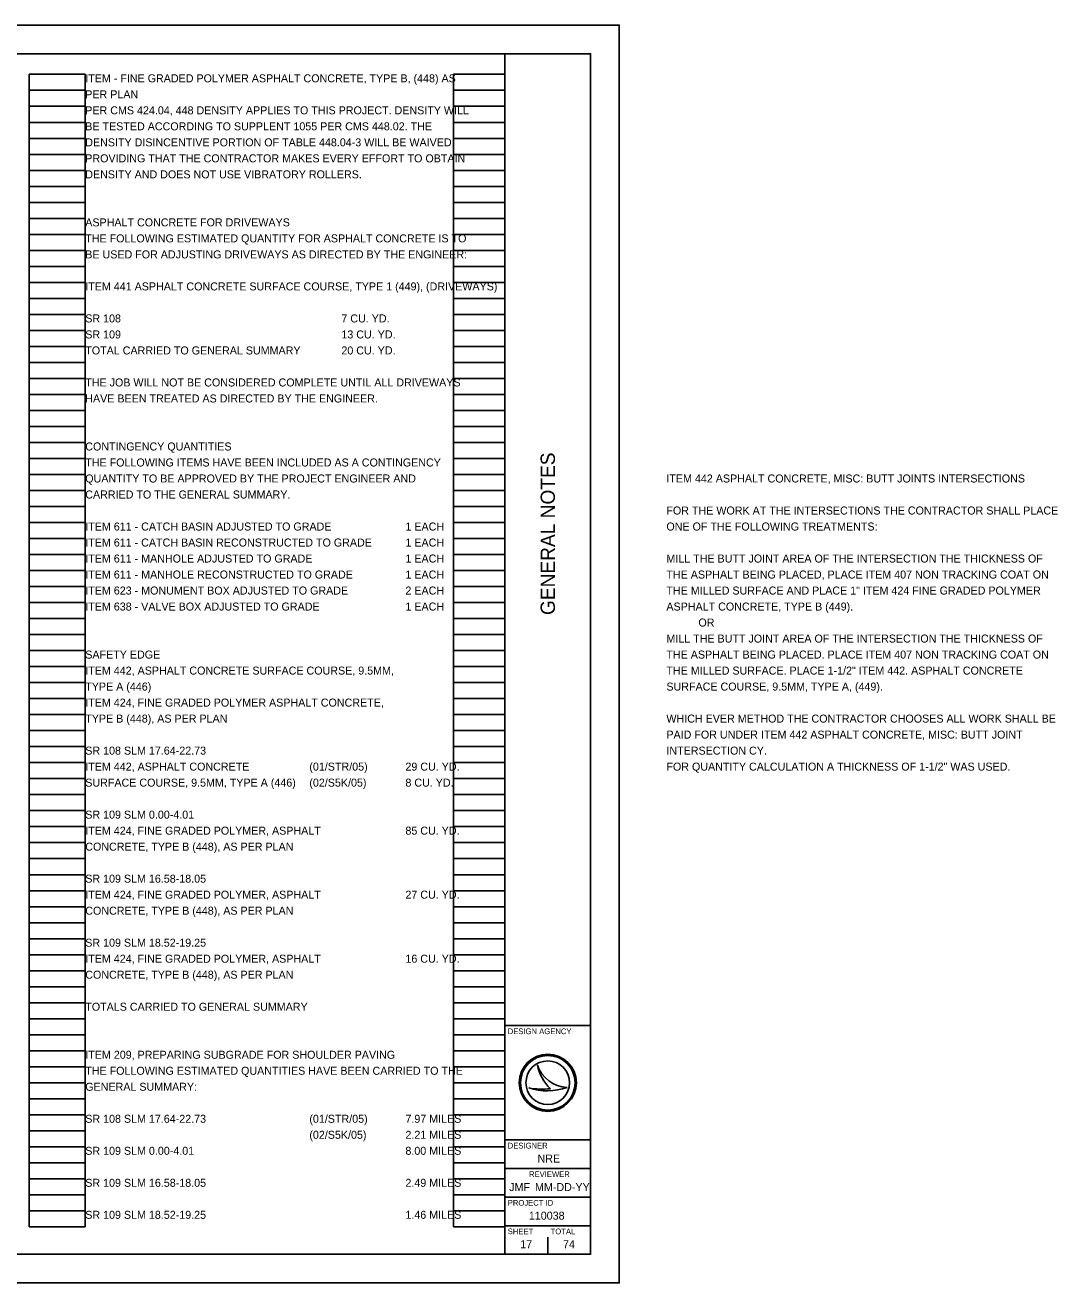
# Model space of a CAD drawing. Extents: x -28.8 to 41.7, y 0 to 25.4.
# Drawn here: x 23.61 to 41.67, y 0 to 22 of the extents above; entities that cross this region are included whole.
import ezdxf

# ---------------------------------------------------------------- set-up
doc = ezdxf.new("R2010")
doc.units = 0
for name, color, linetype in [('SH_Border', 7, 'Continuous'), ('SH_Cut_Line', 7, 'Continuous'), ('SH_Data', 7, 'Continuous'), ('SH_Text', 7, 'Continuous')]:
    doc.layers.add(name, color=color, linetype=linetype)

msp = doc.modelspace()

# ---------------------------------------------------------------- linework, layer by layer
at = {"layer": 'SH_Border'}
for p, q in [((32, 0.5), (32, 21.5)), ((32, 4.5), (33.5, 4.5)), ((32, 2.5), (33.5, 2.5)), ((32, 2), (33.5, 2)), ((32, 1.5), (33.5, 1.5)), ((32, 1), (33.5, 1))]:
    msp.add_line(p, q, dxfattribs=at)
msp.add_lwpolyline([(1.5, 21.5), (33.5, 21.5), (33.5, 0.5), (1.5, 0.5)], close=True, dxfattribs=at)
at = {"layer": 'SH_Cut_Line'}
msp.add_lwpolyline([(0, 0), (34, 0), (34, 22), (0, 22)], close=True, dxfattribs=at)
at = {"layer": 'SH_Data'}
for p, q in [((23.68, 0.98), (23.68, 21.14)), ((23.68, 21.14), (24.66, 21.14)), ((24.66, 0.98), (24.66, 21.14)), ((31.1, 0.98), (31.1, 21.14)), ((31.1, 21.14), (32, 21.14)), ((32, 0.98), (32, 21.14)), ((23.68, 20.86), (24.66, 20.86)), ((31.1, 20.86), (32, 20.86)), ((23.68, 20.58), (24.66, 20.58)), ((31.1, 20.58), (32, 20.58)), ((23.68, 20.3), (24.66, 20.3)), ((31.1, 20.3), (32, 20.3)), ((23.68, 20.02), (24.66, 20.02)), ((31.1, 20.02), (32, 20.02)), ((23.68, 19.74), (24.66, 19.74)), ((31.1, 19.74), (32, 19.74)), ((23.68, 19.46), (24.66, 19.46)), ((31.1, 19.46), (32, 19.46)), ((23.68, 19.18), (24.66, 19.18)), ((31.1, 19.18), (32, 19.18)), ((23.68, 18.9), (24.66, 18.9)), ((31.1, 18.9), (32, 18.9)), ((23.68, 18.62), (24.66, 18.62)), ((31.1, 18.62), (32, 18.62)), ((23.68, 18.34), (24.66, 18.34)), ((31.1, 18.34), (32, 18.34)), ((23.68, 18.06), (24.66, 18.06)), ((31.1, 18.06), (32, 18.06)), ((23.68, 17.78), (24.66, 17.78)), ((31.1, 17.78), (32, 17.78)), ((23.68, 17.5), (24.66, 17.5)), ((31.1, 17.5), (32, 17.5)), ((23.68, 17.22), (24.66, 17.22)), ((31.1, 17.22), (32, 17.22)), ((23.68, 16.94), (24.66, 16.94)), ((31.1, 16.94), (32, 16.94)), ((23.68, 16.66), (24.66, 16.66)), ((31.1, 16.66), (32, 16.66)), ((23.68, 16.38), (24.66, 16.38)), ((31.1, 16.38), (32, 16.38)), ((23.68, 16.1), (24.66, 16.1)), ((31.1, 16.1), (32, 16.1)), ((23.68, 15.82), (24.66, 15.82)), ((31.1, 15.82), (32, 15.82)), ((23.68, 15.54), (24.66, 15.54)), ((31.1, 15.54), (32, 15.54)), ((23.68, 15.26), (24.66, 15.26)), ((31.1, 15.26), (32, 15.26)), ((23.68, 14.98), (24.66, 14.98)), ((31.1, 14.98), (32, 14.98)), ((23.68, 14.7), (24.66, 14.7)), ((31.1, 14.7), (32, 14.7)), ((23.68, 14.42), (24.66, 14.42)), ((31.1, 14.42), (32, 14.42)), ((23.68, 14.14), (24.66, 14.14)), ((31.1, 14.14), (32, 14.14)), ((23.68, 13.86), (24.66, 13.86)), ((31.1, 13.86), (32, 13.86)), ((23.68, 13.58), (24.66, 13.58)), ((31.1, 13.58), (32, 13.58)), ((23.68, 13.3), (24.66, 13.3)), ((31.1, 13.3), (32, 13.3)), ((23.68, 13.02), (24.66, 13.02)), ((31.1, 13.02), (32, 13.02)), ((23.68, 12.74), (24.66, 12.74)), ((31.1, 12.74), (32, 12.74)), ((23.68, 12.46), (24.66, 12.46)), ((31.1, 12.46), (32, 12.46)), ((23.68, 12.18), (24.66, 12.18)), ((31.1, 12.18), (32, 12.18)), ((23.68, 11.9), (24.66, 11.9)), ((31.1, 11.9), (32, 11.9)), ((23.68, 11.62), (24.66, 11.62)), ((31.1, 11.62), (32, 11.62)), ((23.68, 11.34), (24.66, 11.34)), ((31.1, 11.34), (32, 11.34)), ((23.68, 11.06), (24.66, 11.06)), ((31.1, 11.06), (32, 11.06)), ((23.68, 10.78), (24.66, 10.78)), ((31.1, 10.78), (32, 10.78)), ((23.68, 10.5), (24.66, 10.5)), ((31.1, 10.5), (32, 10.5)), ((23.68, 10.22), (24.66, 10.22)), ((31.1, 10.22), (32, 10.22)), ((23.68, 9.94), (24.66, 9.94)), ((31.1, 9.94), (32, 9.94)), ((23.68, 9.66), (24.66, 9.66)), ((31.1, 9.66), (32, 9.66)), ((23.68, 9.38), (24.66, 9.38)), ((31.1, 9.38), (32, 9.38)), ((23.68, 9.1), (24.66, 9.1)), ((31.1, 9.1), (32, 9.1)), ((23.68, 8.82), (24.66, 8.82)), ((31.1, 8.82), (32, 8.82)), ((23.68, 8.54), (24.66, 8.54)), ((31.1, 8.54), (32, 8.54)), ((23.68, 8.26), (24.66, 8.26)), ((31.1, 8.26), (32, 8.26)), ((23.68, 7.98), (24.66, 7.98)), ((31.1, 7.98), (32, 7.98)), ((23.68, 7.7), (24.66, 7.7)), ((31.1, 7.7), (32, 7.7)), ((23.68, 7.42), (24.66, 7.42)), ((31.1, 7.42), (32, 7.42)), ((23.68, 7.14), (24.66, 7.14)), ((31.1, 7.14), (32, 7.14)), ((23.68, 6.86), (24.66, 6.86)), ((31.1, 6.86), (32, 6.86)), ((23.68, 6.58), (24.66, 6.58)), ((31.1, 6.58), (32, 6.58)), ((23.68, 6.3), (24.66, 6.3)), ((31.1, 6.3), (32, 6.3)), ((23.68, 6.02), (24.66, 6.02)), ((31.1, 6.02), (32, 6.02)), ((23.68, 5.74), (24.66, 5.74)), ((31.1, 5.74), (32, 5.74)), ((23.68, 5.46), (24.66, 5.46)), ((31.1, 5.46), (32, 5.46)), ((23.68, 5.18), (24.66, 5.18)), ((31.1, 5.18), (32, 5.18)), ((23.68, 4.9), (24.66, 4.9)), ((31.1, 4.9), (32, 4.9)), ((23.68, 4.62), (24.66, 4.62)), ((31.1, 4.62), (32, 4.62)), ((23.68, 4.34), (24.66, 4.34)), ((31.1, 4.34), (32, 4.34)), ((23.68, 4.06), (24.66, 4.06)), ((31.1, 4.06), (32, 4.06)), ((23.68, 3.78), (24.66, 3.78)), ((31.1, 3.78), (32, 3.78)), ((32.567, 3.81), (32.567, 3.81)), ((23.68, 3.5), (24.66, 3.5)), ((31.1, 3.5), (32, 3.5)), ((32.417, 3.41), (32.417, 3.41)), ((32.75, 3.5), (32.75, 3.5)), ((33.087, 3.419), (33.087, 3.419)), ((23.68, 3.22), (24.66, 3.22)), ((31.1, 3.22), (32, 3.22)), ((23.68, 2.94), (24.66, 2.94)), ((31.1, 2.94), (32, 2.94)), ((23.68, 2.66), (24.66, 2.66)), ((31.1, 2.66), (32, 2.66)), ((23.68, 2.38), (24.66, 2.38)), ((31.1, 2.38), (32, 2.38)), ((23.68, 2.1), (24.66, 2.1)), ((31.1, 2.1), (32, 2.1)), ((23.68, 1.82), (24.66, 1.82)), ((31.1, 1.82), (32, 1.82)), ((23.68, 1.54), (24.66, 1.54)), ((31.1, 1.54), (32, 1.54)), ((23.68, 1.26), (24.66, 1.26)), ((31.1, 1.26), (32, 1.26)), ((23.68, 0.98), (24.66, 0.98)), ((31.1, 0.98), (32, 0.98)), ((32.375, 0.675), (32.375, 0.675)), ((32.75, 0.5), (32.75, 0.8))]:
    msp.add_line(p, q, dxfattribs=at)
for radius in [0.5, 0.477, 0.477, 0.382]:
    msp.add_circle((32.75, 3.5), radius, dxfattribs=at)
for centre, radius, start, end in [((33.116, 3.998), 0.58, 198.9257, 198.9319), ((33.347, 3.97), 0.796, 191.6379, 191.6421), ((33.116, 3.998), 0.58, 198.9319, 267.1657), ((33.347, 3.97), 0.796, 191.6421, 226.0947), ((32.739, 4.37), 1.013, 251.4576, 290.0832), ((32.648, 4.654), 1.266, 259.4964, 259.4995), ((32.739, 4.37), 1.013, 251.4527, 251.4576), ((32.648, 4.654), 1.266, 259.4995, 276.6672)]:
    msp.add_arc(centre, radius, start, end, dxfattribs=at)

# ---------------------------------------------------------------- texts
msp.add_text('GENERAL NOTES', height=0.25, rotation=90, dxfattribs=at).set_placement((32.875, 11.682))
for s, height, p in [('DESIGN AGENCY', 0.1, (32.05, 4.35)), ('DESIGNER', 0.1, (32.05, 2.35)), ('NRE', 0.14, (32.571, 2.105)), ('REVIEWER', 0.1, (32.422, 1.85)), ('JMF', 0.14, (32.075, 1.605)), ('MM-DD-YY', 0.14, (32.527, 1.605)), ('PROJECT ID', 0.1, (32.05, 1.35)), ('110038', 0.14, (32.419, 1.105)), ('SHEET', 0.1, (32.05, 0.85)), ('TOTAL', 0.1, (32.8, 0.85)), ('17', 0.14, (32.268, 0.605)), ('74', 0.14, (33.016, 0.605))]:
    msp.add_text(s, height=height, dxfattribs=at).set_placement(p)
at = {"layer": 'SH_Text'}
for s, p in [('ITEM - FINE GRADED POLYMER ASPHALT CONCRETE, TYPE B, (448) AS', (24.66, 21)), ('PER PLAN', (24.66, 20.72)), ('PER CMS 424.04, 448 DENSITY APPLIES TO THIS PROJECT. DENSITY WILL', (24.66, 20.44)), ('BE TESTED ACCORDING TO SUPPLENT 1055 PER CMS 448.02. THE', (24.66, 20.16)), ('DENSITY DISINCENTIVE PORTION OF TABLE 448.04-3 WILL BE WAIVED', (24.66, 19.88)), ('PROVIDING THAT THE CONTRACTOR MAKES EVERY EFFORT TO OBTAIN', (24.66, 19.6)), ('DENSITY AND DOES NOT USE VIBRATORY ROLLERS.', (24.66, 19.32)), ('ASPHALT CONCRETE FOR DRIVEWAYS', (24.66, 18.48)), ('THE FOLLOWING ESTIMATED QUANTITY FOR ASPHALT CONCRETE IS TO', (24.66, 18.2)), ('BE USED FOR ADJUSTING DRIVEWAYS AS DIRECTED BY THE ENGINEER:', (24.66, 17.92)), ('ITEM 441 ASPHALT CONCRETE SURFACE COURSE, TYPE 1 (449), (DRIVEWAYS)', (24.66, 17.36)), ('SR 108', (24.66, 16.8)), ('7 CU. YD.', (29.14, 16.8)), ('SR 109', (24.66, 16.52)), ('13 CU. YD.', (29.14, 16.52)), ('TOTAL CARRIED TO GENERAL SUMMARY', (24.66, 16.24)), ('20 CU. YD.', (29.14, 16.24)), ('THE JOB WILL NOT BE CONSIDERED COMPLETE UNTIL ALL DRIVEWAYS', (24.66, 15.68)), ('HAVE BEEN TREATED AS DIRECTED BY THE ENGINEER.', (24.66, 15.4)), ('CONTINGENCY QUANTITIES', (24.66, 14.56)), ('THE FOLLOWING ITEMS HAVE BEEN INCLUDED AS A CONTINGENCY', (24.66, 14.28)), ('QUANTITY TO BE APPROVED BY THE PROJECT ENGINEER AND', (24.66, 14)), ('ITEM 442 ASPHALT CONCRETE, MISC: BUTT JOINTS INTERSECTIONS', (34.825, 14)), ('CARRIED TO THE GENERAL SUMMARY.', (24.66, 13.72)), ('FOR THE WORK AT THE INTERSECTIONS THE CONTRACTOR SHALL PLACE', (34.825, 13.44)), ('ITEM 611 - CATCH BASIN ADJUSTED TO GRADE', (24.66, 13.16)), ('1 EACH', (30.26, 13.16)), ('ONE OF THE FOLLOWING TREATMENTS:', (34.825, 13.16)), ('ITEM 611 - CATCH BASIN RECONSTRUCTED TO GRADE', (24.66, 12.88)), ('1 EACH', (30.26, 12.88)), ('ITEM 611 - MANHOLE ADJUSTED TO GRADE', (24.66, 12.6)), ('1 EACH', (30.26, 12.6)), ('MILL THE BUTT JOINT AREA OF THE INTERSECTION THE THICKNESS OF', (34.825, 12.6)), ('ITEM 611 - MANHOLE RECONSTRUCTED TO GRADE', (24.66, 12.32)), ('1 EACH', (30.26, 12.32)), ('THE ASPHALT BEING PLACED, PLACE ITEM 407 NON TRACKING COAT ON', (34.825, 12.32)), ('ITEM 623 - MONUMENT BOX ADJUSTED TO GRADE', (24.66, 12.04)), ('2 EACH', (30.26, 12.04)), ('THE MILLED SURFACE AND PLACE 1" ITEM 424 FINE GRADED POLYMER', (34.825, 12.04)), ('ITEM 638 - VALVE BOX ADJUSTED TO GRADE', (24.66, 11.76)), ('1 EACH', (30.26, 11.76)), ('ASPHALT CONCRETE, TYPE B (449).', (34.825, 11.76)), ('OR', (35.385, 11.48)), ('MILL THE BUTT JOINT AREA OF THE INTERSECTION THE THICKNESS OF', (34.825, 11.2)), ('SAFETY EDGE', (24.66, 10.92)), ('THE ASPHALT BEING PLACED. PLACE ITEM 407 NON TRACKING COAT ON', (34.825, 10.92)), ('ITEM 442, ASPHALT CONCRETE SURFACE COURSE, 9.5MM,', (24.66, 10.64)), ('THE MILLED SURFACE. PLACE 1-1/2" ITEM 442. ASPHALT CONCRETE', (34.825, 10.64)), ('TYPE A (446)', (24.66, 10.36)), ('SURFACE COURSE, 9.5MM, TYPE A, (449).', (34.825, 10.36)), ('ITEM 424, FINE GRADED POLYMER ASPHALT CONCRETE,', (24.66, 10.08)), ('TYPE B (448), AS PER PLAN', (24.66, 9.8)), ('WHICH EVER METHOD THE CONTRACTOR CHOOSES ALL WORK SHALL BE', (34.825, 9.8)), ('PAID FOR UNDER ITEM 442 ASPHALT CONCRETE, MISC: BUTT JOINT', (34.825, 9.52)), ('SR 108 SLM 17.64-22.73', (24.66, 9.24)), ('INTERSECTION CY.', (34.825, 9.24)), ('ITEM 442, ASPHALT CONCRETE', (24.66, 8.96)), ('(01/STR/05)', (28.58, 8.96)), ('29 CU. YD.', (30.26, 8.96)), ('FOR QUANTITY CALCULATION A THICKNESS OF 1-1/2" WAS USED.', (34.825, 8.96)), ('SURFACE COURSE, 9.5MM, TYPE A (446)', (24.66, 8.68)), ('(02/S5K/05)', (28.58, 8.68)), ('8 CU. YD.', (30.26, 8.68)), ('SR 109 SLM 0.00-4.01', (24.66, 8.12)), ('ITEM 424, FINE GRADED POLYMER, ASPHALT', (24.66, 7.84)), ('85 CU. YD.', (30.26, 7.84)), ('CONCRETE, TYPE B (448), AS PER PLAN', (24.66, 7.56)), ('SR 109 SLM 16.58-18.05', (24.66, 7)), ('ITEM 424, FINE GRADED POLYMER, ASPHALT', (24.66, 6.72)), ('27 CU. YD.', (30.26, 6.72)), ('CONCRETE, TYPE B (448), AS PER PLAN', (24.66, 6.44)), ('SR 109 SLM 18.52-19.25', (24.66, 5.88)), ('ITEM 424, FINE GRADED POLYMER, ASPHALT', (24.66, 5.6)), ('16 CU. YD.', (30.26, 5.6)), ('CONCRETE, TYPE B (448), AS PER PLAN', (24.66, 5.32)), ('TOTALS CARRIED TO GENERAL SUMMARY', (24.66, 4.76)), ('ITEM 209, PREPARING SUBGRADE FOR SHOULDER PAVING', (24.66, 3.92)), ('THE FOLLOWING ESTIMATED QUANTITIES HAVE BEEN CARRIED TO THE', (24.66, 3.64)), ('GENERAL SUMMARY:', (24.66, 3.36)), ('SR 108 SLM 17.64-22.73', (24.66, 2.8)), ('(01/STR/05)', (28.58, 2.8)), ('7.97 MILES', (30.26, 2.8)), ('(02/S5K/05)', (28.58, 2.52)), ('2.21 MILES', (30.26, 2.52)), ('SR 109 SLM 0.00-4.01', (24.66, 2.24)), ('8.00 MILES', (30.26, 2.24)), ('SR 109 SLM 16.58-18.05', (24.66, 1.68)), ('2.49 MILES', (30.26, 1.68)), ('SR 109 SLM 18.52-19.25', (24.66, 1.12)), ('1.46 MILES', (30.26, 1.12))]:
    msp.add_text(s, height=0.14, dxfattribs=at).set_placement(p)

doc.saveas('drawing.dxf')
